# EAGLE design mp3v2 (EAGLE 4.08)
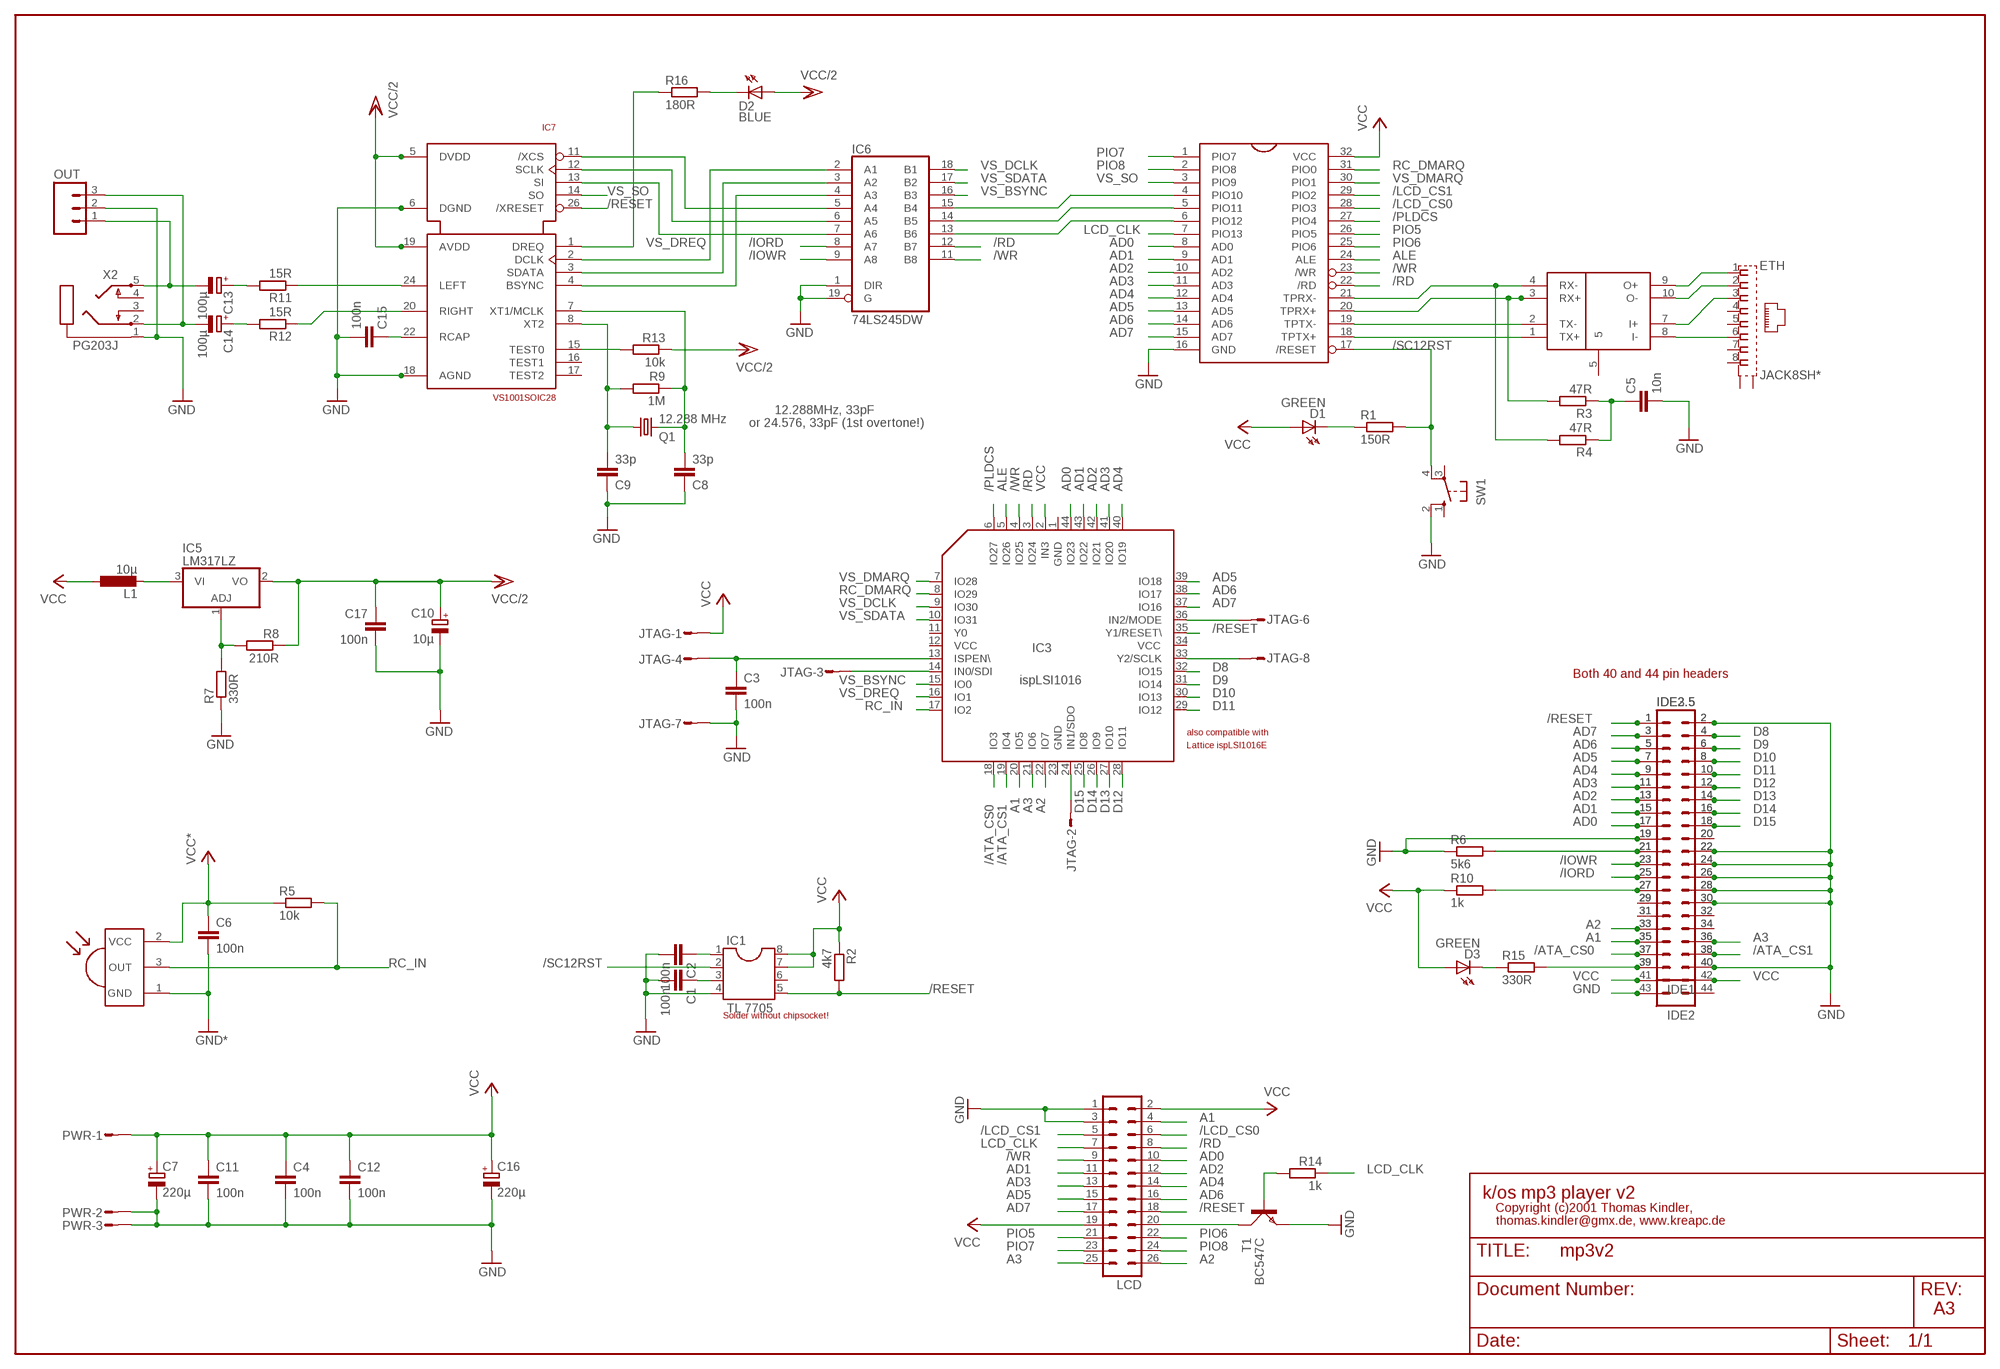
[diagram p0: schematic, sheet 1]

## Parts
C1  100n  C-EU025-024X044  [C025-024X044]
C2  100n  C-EU025-024X044  [C025-024X044]
C3  100n  C-EU025-024X044  [C025-024X044]
C4  100n  C-EU025-024X044  [C025-024X044]
C5  10n  C-EU025-024X044  [C025-024X044]
C6  100n  C-EU025-024X044  [C025-024X044]
C7  220µ  CPOL-EUE3.5-8  [E3,5-8]
C8  33p  C-EU025-024X044  [C025-024X044]
C9  33p  C-EU025-024X044  [C025-024X044]
C10  10µ  CPOL-EUE2.5-5  [E2,5-5]
C11  100n  C-EU025-024X044  [C025-024X044]
C12  100n  C-EU025-024X044  [C025-024X044]
C13  100µ  CPOL-EUE2.5-6  [E2,5-6]
C14  100µ  CPOL-EUE2.5-6  [E2,5-6]
C15  100n  C-EU025-024X044  [C025-024X044]
C16  220µ  CPOL-EUE3.5-8  [E3,5-8]
C17  100n  C-EU025-024X044  [C025-024X044]
D1  GREEN  LED3MM  [LED3MM]
D2  BLUE  LED3MM  [LED3MM]
D3  GREEN  LED3MM  [LED3MM]
ETH  JACK8SH*  [RJ45_8]
HALO  HALO  FS22-101Y4SIP10  [SIP10]
IC1  TL 7705  DIL8  [DIL08]
IC2  SC12  SC12FATDIL32  [FATDIL32]
IC3  ispLSI1016  LSI1016J  [PLCC44]
IC4  TSOP17XX*  [TSOP]
IC5  LM317LZ  [TO92@1]
IC6  74LS245DW  [SO20W]
IC7  VS1001SOIC28  [SOIC28]
IDE1  IDE3.5  ML40  [ML40]
IDE2  IDE2.5  ML44_2MM  [ML44_2MM]
JTAG  M08S  [08P]
L1  10µ  L-EU0207/12  [0207/12]
LCD  ML26  [ML26]
OUT  M03  [03P]
PWR  M03S  [03P]
Q1  12.288 MHz  HC49U-V  [HC49U-V]
R1  150R  R-EU_0207/2V  [0207/2V]
R2  4k7  R-EU_0207/2V  [0207/2V]
R3  47R  R-EU_0207/2V  [0207/2V]
R4  47R  R-EU_0207/2V  [0207/2V]
R5  10k  R-EU_0207/2V  [0207/2V]
R6  5k6  R-EU_0207/2V  [0207/2V]
R7  330R  R-EU_0207/2V  [0207/2V]
R8  210R  R-EU_0207/2V  [0207/2V]
R9  1M  R-EU_0207/2V  [0207/2V]
R10  1k  R-EU_0207/2V  [0207/2V]
R11  15R  R-EU_0207/2V  [0207/2V]
R12  15R  R-EU_0207/2V  [0207/2V]
R13  10k  R-EU_0207/2V  [0207/2V]
R14  1k  R-EU_0207/2V  [0207/2V]
R15  330R  R-EU_0207/2V  [0207/2V]
R16  180R  R-EU_0207/2V  [0207/2V]
SW1  10-XX  [B3F-10XX]
T1  BC547C  BC547  [SOT54A]
X2  PG203J  [PG203J]

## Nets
/ATA_CS0: IC3.18(IO3) IDE1.37 IDE2.37
/ATA_CS1: IC3.19(IO4) IDE1.38 IDE2.38
/IORD: IC6.8(A7) IDE1.25 IDE2.25
/IOWR: IC6.9(A8) IDE1.23 IDE2.23
/LCD_CS0: IC2.28(PIO3) LCD.6
/LCD_CS1: IC2.29(PIO2) LCD.5
/PLDCS: IC2.27(PIO4) IC3.6(IO27)
/RD: IC2.22(/RD) IC3.3(IO24) IC6.12(B7) LCD.8
/RESET: IC1.5 IC3.35(Y1/RESET\) IC7.26(/XRESET) IDE1.1 IDE2.1 LCD.18 R2.2
/SC12RST: IC1.2 IC2.17(/RESET) R1.2 SW1.4(P1)
/VS_CS: IC2.6(PIO12) IC6.13(B6)
/WR: IC2.23(/WR) IC3.4(IO25) IC6.11(B8) LCD.9
A1: IC3.20(IO5) IDE1.35 IDE2.35 LCD.4
A2: IC3.22(IO7) IDE1.33 IDE2.33 LCD.26
A3: IC3.21(IO6) IDE1.36 IDE2.36 LCD.25
AD0: IC2.8(AD0) IC3.44(IO23) IDE1.17 IDE2.17 LCD.10
AD1: IC2.9(AD1) IC3.43(IO22) IDE1.15 IDE2.15 LCD.11
AD2: IC2.10(AD2) IC3.42(IO21) IDE1.13 IDE2.13 LCD.12
AD3: IC2.11(AD3) IC3.41(IO20) IDE1.11 IDE2.11 LCD.13
AD4: IC2.12(AD4) IC3.40(IO19) IDE1.9 IDE2.9 LCD.14
AD5: IC2.13(AD5) IC3.39(IO18) IDE1.7 IDE2.7 LCD.15
AD6: IC2.14(AD6) IC3.38(IO17) IDE1.5 IDE2.5 LCD.16
AD7: IC2.15(AD7) IC3.37(IO16) IDE1.3 IDE2.3 LCD.17
ALE: IC2.24(ALE) IC3.5(IO26)
D8: IC3.32(IO15) IDE1.4 IDE2.4
D9: IC3.31(IO14) IDE1.6 IDE2.6
D10: IC3.30(IO13) IDE1.8 IDE2.8
D11: IC3.29(IO12) IDE1.10 IDE2.10
D12: IC3.28(IO11) IDE1.12 IDE2.12
D13: IC3.27(IO10) IDE1.14 IDE2.14
D14: IC3.26(IO9) IDE1.16 IDE2.16
D15: IC3.25(IO8) IDE1.18 IDE2.18
GND: C1.2 C2.2 C3.2 C4.2 C5.2 C6.2 C7.- C8.1 C9.1 C10.- C11.2 C12.2 C15.2 C16.- C17.2 IC1.4 IC2.16(GND) IC4.1(GND) IC6.1(DIR) IC6.19(G) IC7.6(DGND) IC7.10(DGND) IC7.18(AGND) IC7.21(AGND) IC7.25(AGND) IC7.27(DGND) IDE1.2 IDE1.19 IDE1.22 IDE1.24 IDE1.26 IDE1.28 IDE1.30 IDE1.40 IDE2.2 IDE2.19 IDE2.22 IDE2.24 IDE2.26 IDE2.28 IDE2.30 IDE2.40 IDE2.43 JTAG.7 LCD.1 LCD.3 OUT.2 PWR.2 PWR.3 R6.1 R7.1 SW1.2(S1) T1.E X2.1 ; supply symbol labelled GND*
LCD_CLK: IC2.7(PIO13) LCD.7 R14.1
LEFT: C13.- OUT.1 X2.5
N$1: C8.2 IC7.7(XT1/MCLK) Q1.2 R9.1
N$2: C14.+ R12.2
N$3: IDE1.39 IDE2.39 R15.2
N$4: IC6.2(A1) IC7.2(DCLK)
N$5: IC5.1(ADJ) R7.2 R8.2
N$6: HALO.4(RX-) IC2.21(TPRX-) R4.2
N$7: LCD.20 T1.C
N$8: IC7.24(LEFT) R11.1
N$9: IC7.15(TEST0) R13.2
N$10: IC6.3(A2) IC7.3(SDATA)
N$11: C15.1 IC7.22(RCAP)
N$12: C13.+ R11.2
N$13: IC7.20(RIGHT) R12.1
N$14: IC6.4(A3) IC7.4(BSYNC)
N$15: IC6.5(A4) IC7.11(/XCS)
N$16: IC6.6(A5) IC7.12(SCLK)
N$17: HALO.2(TX-) IC2.19(TPTX-)
N$18: HALO.3(RX+) IC2.20(TPRX+) R3.2
N$20: HALO.1(TX+) IC2.18(TPTX+)
N$21: ETH.1 HALO.9(O+)
N$22: ETH.2 HALO.10(O-)
N$23: ETH.3 HALO.7(I+)
N$24: ETH.6 HALO.8(I-)
N$25: C5.1 R3.1 R4.1
N$26: IC6.7(A6) IC7.13(SI)
N$27: D3.K(C) R15.1
N$28: C1.1 IC1.3
N$29: IDE1.27 IDE2.27 R10.2
N$30: C3.1 IC3.13(ISPEN\) JTAG.4
N$31: IDE1.21 IDE2.21 R6.2
N$32: C9.2 IC7.8(XT2) Q1.1 R9.2
N$33: IC3.14(IN0/SDI) JTAG.3
N$34: IC3.24(IN1/SDO) JTAG.2
N$35: IC3.36(IN2/MODE) JTAG.6
N$36: IC3.33(Y2/SCLK) JTAG.8
N$38: D2.K(C) R16.2
N$39: R14.2 T1.B
N$40: IC5.3(VI) L1.2
N$42: IDE1.29 IDE2.29
N$43: IDE1.31 IDE2.31
N$44: IDE1.20 IDE2.20
N$45: IDE1.32 IDE2.32
N$46: IDE1.34 IDE2.34
N$47: C2.1 IC1.1
N$49: D1.K(C) R1.1
PIO5: IC2.26(PIO5) LCD.21
PIO6: IC2.25(PIO6) LCD.22
PIO7: IC2.1(PIO7) LCD.23
PIO8: IC2.2(PIO8) LCD.24
RC_DMARQ: IC2.31(PIO0) IC3.8(IO29)
RC_IN: IC3.17(IO2) IC4.3(OUT) R5.2
RIGHT: C14.- OUT.3 X2.2
VCC: C4.1 C6.1 C7.+ C11.1 C12.1 C16.+ D1.A D3.A IC1.7 IC1.8 IC2.32(VCC) IC3.2(IN3) IC4.2(VCC) IDE2.41 IDE2.42 JTAG.1 L1.1 LCD.2 LCD.19 PWR.1 R2.1 R5.1 R10.1 ; supply symbol labelled VCC*
VCC/2: C10.+ C17.1 D2.A IC5.2(VO) IC7.5(DVDD) IC7.9(DVDD) IC7.19(AVDD) IC7.23(AVDD) IC7.28(DVDD) R8.1 R13.1
VS_BSYNC: IC3.15(IO0) IC6.16(B3)
VS_DCLK: IC3.9(IO30) IC6.18(B1)
VS_DMARQ: IC2.30(PIO1) IC3.7(IO28)
VS_DREQ: IC3.16(IO1) IC7.1(DREQ) R16.1
VS_SCLK: IC2.5(PIO11) IC6.14(B5)
VS_SDATA: IC3.10(IO31) IC6.17(B2)
VS_SI: IC2.4(PIO10) IC6.15(B4)
VS_SO: IC2.3(PIO9) IC7.14(SO)
Unconnected: ETH.4 ETH.5 ETH.7 ETH.8 ETH.SH1(S1) ETH.SH2(S2) HALO.5 IC1.6 IC3.11(Y0) IC7.16(TEST1) IC7.17(TEST2) IDE2.44 JTAG.5 SW1.1(S) SW1.3(P) X2.3 X2.4

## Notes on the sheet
- 12.288MHz, 33pF
- or 24.576, 33pF (1st overtone!)
- Both 40 and 44 pin headers
- also compatible with
- Lattice ispLSI1016E
- Solder without chipsocket!
- k/os mp3 player v2
- Copyright (c)2001 Thomas Kindler,
- thomas.kindler@gmx.de, www.kreapc.de
- A3

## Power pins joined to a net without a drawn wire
GND: IC3.1(GND) IC3.23(GND) IC6.10(GND)
VCC: IC3.12(VCC) IC3.34(VCC) IC6.20(VCC)

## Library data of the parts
C1-C6 C8 C9 C11 C12 C15 C17 = rcl:C-EU: CAPACITOR, European symbol
C7 C10 C13 C14 C16 = rcl:CPOL-EU: POLARIZED CAPACITOR, European symbol
D1-D3 = led:LED3MM: LED
ETH = RJ45:JACK8SH
HALO = beck:FS22-101Y4
IC1 = dil:DIL8: SOCKET DIL8
IC2 = beck:SC12
IC3 = lattice:LSI1016J: LATTICE PROGRAMMABLE DEVICE
IC4 = vishay:TSOP17XX
IC5 = linear:*317LZ: Positive VOLTAGE REGULATOR
IC6 = 74xx-eu:74*245: Octal BUS TRANSCEIVER, 3-state
IC7 = vlsi:VS1001
IDE1 = con-ml:ML40: HARTING
IDE2 = IDE44:ML44_2MM
JTAG = con-amp-quick:M08S: AMP QUICK CONNECTOR
L1 = rcl:L-EU: INDUCTOR, European symbol
LCD = con-ml:ML26: HARTING
OUT = con-amp-quick:M03: AMP QUICK CONNECTOR
PWR = con-amp-quick:M03S: AMP QUICK CONNECTOR
Q1 = crystal:HC49U-V: CRYSTAL
R1-R16 = rcl:R-EU_: RESISTOR, European symbol
SW1 = switch-omron:10-XX: OMRON SWITCH
T1 = transistor-small-signal:BC547: NPN TRANSISTOR
X2 = con-hirschmann:PG203J: MIC/HEADPHONE JACK KS-S stereo microphone/headphone jack PG203JN (Schukat)

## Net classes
0 default: width 0.254 mm
1 power: width 0.61 mm

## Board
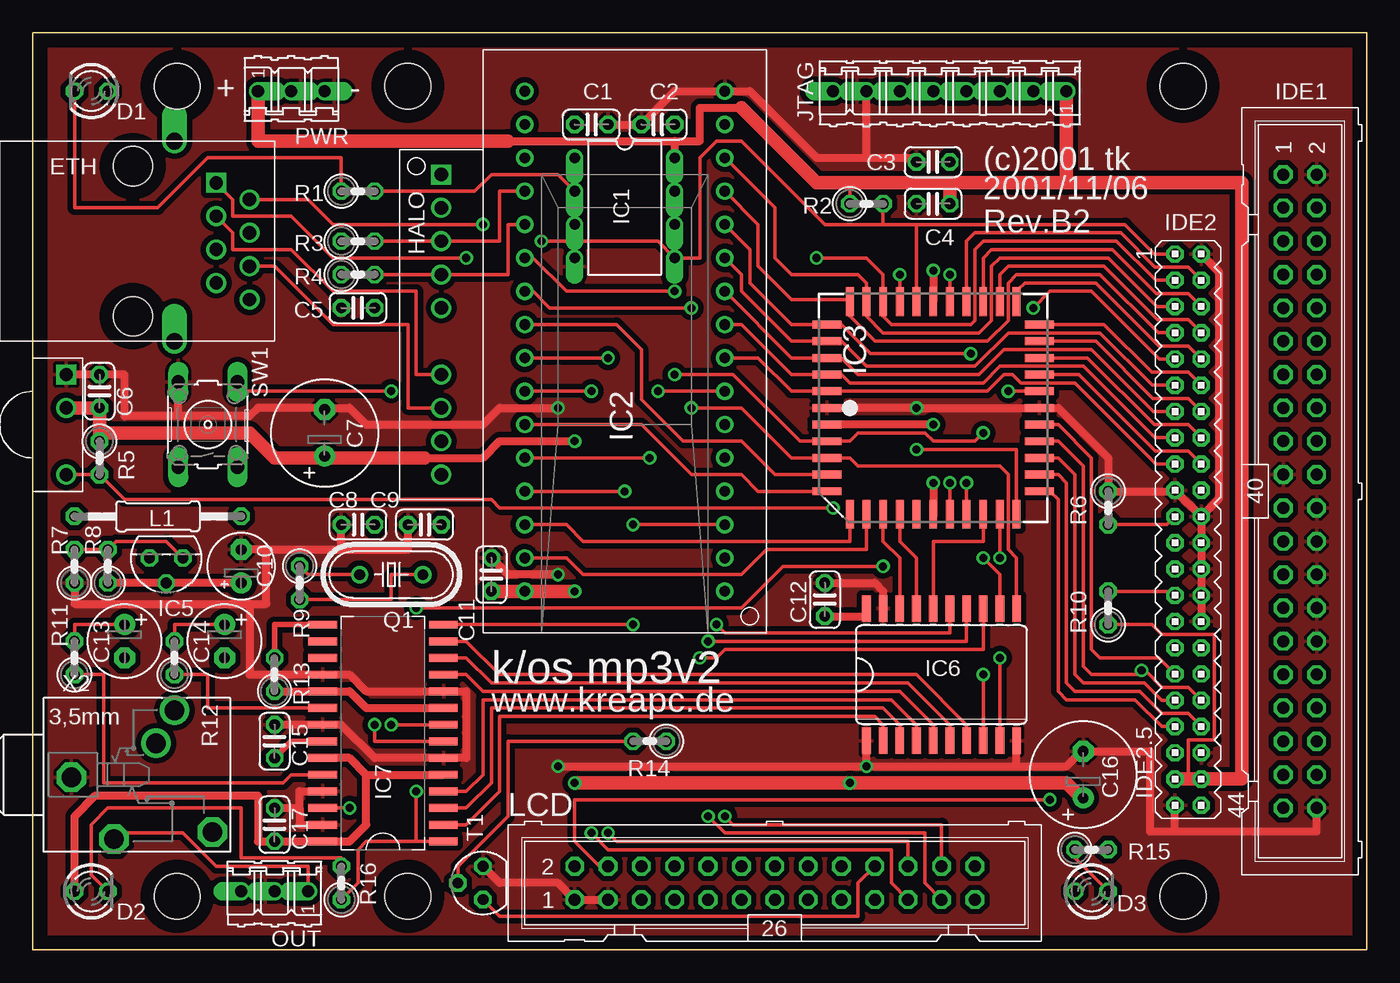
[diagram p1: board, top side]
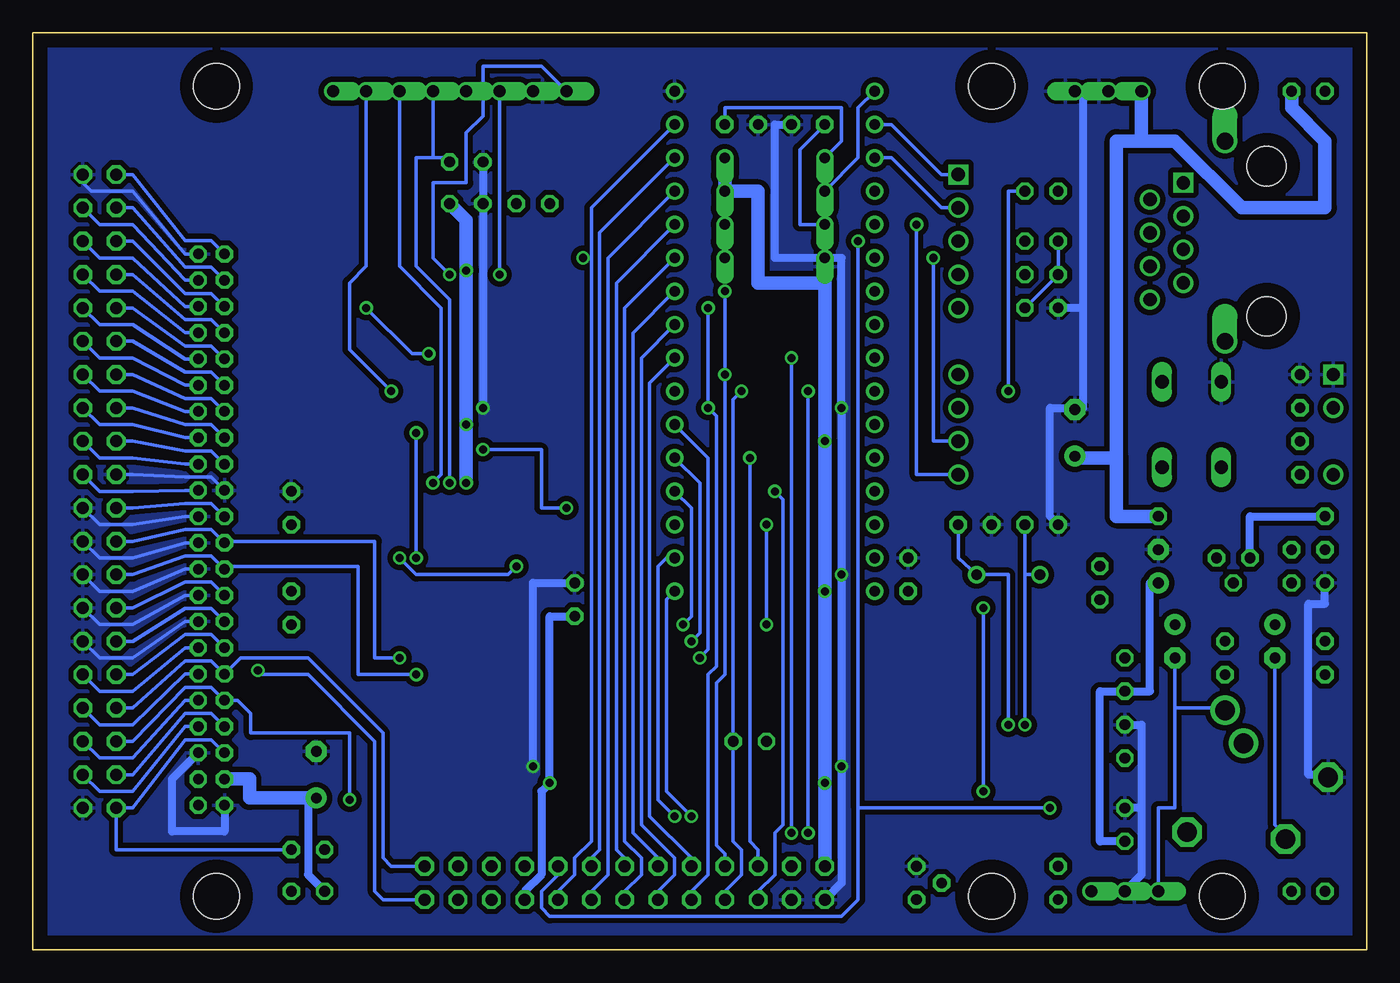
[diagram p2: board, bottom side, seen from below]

Size 101.6 x 69.85 mm. Coordinates in mm from the lower left corner, seen from the top.
Outline: 0,0 0,69.85 101.6,69.85 101.6,0 0,0
Copper layers used: Top, Bottom
Holes 3.5 mm at 87.6,4.06 11,4.06 28.57,4.06 87.6,65.79 11,65.79 28.57,65.79

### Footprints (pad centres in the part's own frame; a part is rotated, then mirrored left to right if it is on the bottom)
C025-024X044 = drill 0.813 octagon: 1 -1.27,0; 2 1.27,0
E3,5-8 = drill 0.813 pad 1.6 round: + -1.778,0 | drill 0.813 pad 1.6 octagon: - 1.778,0
E2,5-5 = drill 0.813 pad 1.6 round: + -1.27,0 | drill 0.813 pad 1.6 octagon: - 1.27,0
E2,5-6 = drill 0.813 pad 1.6 round: + -1.27,0 | drill 0.813 pad 1.6 octagon: - 1.27,0
LED3MM = drill 0.813 octagon: A -1.27,0; K 1.27,0
RJ45_8 = drill 1.016 square: 1 4.445,-6.35 | drill 1.016 round: 2 3.175,-8.89; 3 1.905,-6.35; 4 0.635,-8.89; 5 -0.635,-6.35; 6 -1.905,-8.89; 7 -3.175,-6.35; 8 -4.445,-8.89 | drill 1.27 offset: SH1 -7.62,-3.175; SH2 7.62,-3.175 | hole 3: -5.715,0; 5.715,0
SIP10 = drill 1.016 square: 1 -12.7,0 | drill 1.016 round: 2 -10.16,0; 3 -7.62,0; 4 -5.08,0; 5 -2.54,0; 7 2.54,0; 8 5.08,0; 9 7.62,0; 10 10.16,0
DIL08 = drill 0.813 offset: 1 -3.81,-3.81; 2 -1.27,-3.81; 3 1.27,-3.81; 4 3.81,-3.81; 5 3.81,3.81; 6 1.27,3.81; 7 -1.27,3.81; 8 -3.81,3.81
FATDIL32 = drill 0.813 round: 1 -19.05,-7.62; 2 -16.51,-7.62; 3 -13.97,-7.62; 4 -11.43,-7.62; 5 -8.89,-7.62; 6 -6.35,-7.62; 7 -3.81,-7.62; 8 -1.27,-7.62; 9 1.27,-7.62; 10 3.81,-7.62; 11 6.35,-7.62; 12 8.89,-7.62; 13 11.43,-7.62; 14 13.97,-7.62; 15 16.51,-7.62; 16 19.05,-7.62; 17 19.05,7.62; 18 16.51,7.62; 19 13.97,7.62; 20 11.43,7.62; 21 8.89,7.62; 22 6.35,7.62; 23 3.81,7.62; 24 1.27,7.62; 25 -1.27,7.62; 26 -3.81,7.62; 27 -6.35,7.62; 28 -8.89,7.62; 29 -11.43,7.62; 30 -13.97,7.62; 31 -16.51,7.62; 32 -19.05,7.62
PLCC44 = smd 0.6 x 2.2: 1 0,8.1; 2 -1.27,8.1; 3 -2.54,8.1; 4 -3.81,8.1; 5 -5.08,8.1; 6 -6.35,8.1; 18 -6.35,-8.1; 19 -5.08,-8.1; 20 -3.81,-8.1; 21 -2.54,-8.1; 22 -1.27,-8.1; 23 0,-8.1; 24 1.27,-8.1; 25 2.54,-8.1; 26 3.81,-8.1; 27 5.08,-8.1; 28 6.35,-8.1; 40 6.35,8.1; 41 5.08,8.1; 42 3.81,8.1; 43 2.54,8.1; 44 1.27,8.1 | smd 2.2 x 0.6: 7 -8.1,6.35; 8 -8.1,5.08; 9 -8.1,3.81; 10 -8.1,2.54; 11 -8.1,1.27; 12 -8.1,0; 13 -8.1,-1.27; 14 -8.1,-2.54; 15 -8.1,-3.81; 16 -8.1,-5.08; 17 -8.1,-6.35; 29 8.1,-6.35; 30 8.1,-5.08; 31 8.1,-3.81; 32 8.1,-2.54; 33 8.1,-1.27; 34 8.1,0; 35 8.1,1.27; 36 8.1,2.54; 37 8.1,3.81; 38 8.1,5.08; 39 8.1,6.35
TSOP = drill 1.016 square: 1 -3.81,1.27 | drill 1.016 round: 2 -1.27,1.27; 3 3.81,1.27
TO92 = drill 0.813 octagon: 1 -1.27,0; 2 0,1.905; 3 1.27,0
SO20W = smd 0.66 x 2.032: 1 -5.715,-5.029; 2 -4.445,-5.029; 3 -3.175,-5.029; 4 -1.905,-5.029; 5 -0.635,-5.029; 6 0.635,-5.029; 7 1.905,-5.029; 8 3.175,-5.029; 9 4.445,-5.029; 10 5.715,-5.029; 11 5.715,5.029; 12 4.445,5.029; 13 3.175,5.029; 14 1.905,5.029; 15 0.635,5.029; 16 -0.635,5.029; 17 -1.905,5.029; 18 -3.175,5.029; 19 -4.445,5.029; 20 -5.715,5.029
SOIC28 = smd 0.6 x 2.2: 1 -8.255,-4.6; 2 -6.985,-4.6; 3 -5.715,-4.6; 4 -4.445,-4.6; 5 -3.175,-4.6; 6 -1.905,-4.6; 7 -0.635,-4.6; 8 0.635,-4.6; 9 1.905,-4.6; 10 3.175,-4.6; 11 4.445,-4.6; 12 5.715,-4.6; 13 6.985,-4.6; 14 8.255,-4.6; 15 8.255,4.6; 16 6.985,4.6; 17 5.715,4.6; 18 4.445,4.6; 19 3.175,4.6; 20 1.905,4.6; 21 0.635,4.6; 22 -0.635,4.6; 23 -1.905,4.6; 24 -3.175,4.6; 25 -4.445,4.6; 26 -5.715,4.6; 27 -6.985,4.6; 28 -8.255,4.6
ML40 = drill 0.914 octagon: 1 -24.13,-1.27; 2 -24.13,1.27; 3 -21.59,-1.27; 4 -21.59,1.27; 5 -19.05,-1.27; 6 -19.05,1.27; 7 -16.51,-1.27; 8 -16.51,1.27; 9 -13.97,-1.27; 10 -13.97,1.27; 11 -11.43,-1.27; 12 -11.43,1.27; 13 -8.89,-1.27; 14 -8.89,1.27; 15 -6.35,-1.27; 16 -6.35,1.27; 17 -3.81,-1.27; 18 -3.81,1.27; 19 -1.27,-1.27; 20 -1.27,1.27; 21 1.27,-1.27; 22 1.27,1.27; 23 3.81,-1.27; 24 3.81,1.27; 25 6.35,-1.27; 26 6.35,1.27; 27 8.89,-1.27; 28 8.89,1.27; 29 11.43,-1.27; 30 11.43,1.27; 31 13.97,-1.27; 32 13.97,1.27; 33 16.51,-1.27; 34 16.51,1.27; 35 19.05,-1.27; 36 19.05,1.27; 37 21.59,-1.27; 38 21.59,1.27; 39 24.13,-1.27; 40 24.13,1.27
ML44_2MM = drill 0.8 octagon: 1 -21,-1; 2 -21,1; 3 -19,-1; 4 -19,1; 5 -17,-1; 6 -17,1; 7 -15,-1; 8 -15,1; 9 -13,-1; 10 -13,1; 11 -11,-1; 12 -11,1; 13 -9,-1; 14 -9,1; 15 -7,-1; 16 -7,1; 17 -5,-1; 18 -5,1; 19 -3,-1; 20 -3,1; 21 -1,-1; 22 -1,1; 23 1,-1; 24 1,1; 25 3,-1; 26 3,1; 27 5,-1; 28 5,1; 29 7,-1; 30 7,1; 31 9,-1; 32 9,1; 33 11,-1; 34 11,1; 35 13,-1; 36 13,1; 37 15,-1; 38 15,1; 39 17,-1; 40 17,1; 41 19,-1; 42 19,1; 43 21,-1; 44 21,1
08P = drill 0.914 offset: 1 -8.89,0; 2 -6.35,0; 3 -3.81,0; 4 -1.27,0; 5 1.27,0; 6 3.81,0; 7 6.35,0; 8 8.89,0
0207/12 = drill 0.813 octagon: 1 -6.35,0; 2 6.35,0
ML26 = drill 0.914 octagon: 1 -15.24,-1.27; 2 -15.24,1.27; 3 -12.7,-1.27; 4 -12.7,1.27; 5 -10.16,-1.27; 6 -10.16,1.27; 7 -7.62,-1.27; 8 -7.62,1.27; 9 -5.08,-1.27; 10 -5.08,1.27; 11 -2.54,-1.27; 12 -2.54,1.27; 13 0,-1.27; 14 0,1.27; 15 2.54,-1.27; 16 2.54,1.27; 17 5.08,-1.27; 18 5.08,1.27; 19 7.62,-1.27; 20 7.62,1.27; 21 10.16,-1.27; 22 10.16,1.27; 23 12.7,-1.27; 24 12.7,1.27; 25 15.24,-1.27; 26 15.24,1.27
03P = drill 0.914 offset: 1 -2.54,0; 2 0,0; 3 2.54,0
HC49U-V = drill 0.813 round: 1 -2.413,0; 2 2.413,0
0207/2V = drill 0.813 octagon: 1 -1.27,0; 2 1.27,0
B3F-10XX = drill 1.016 long: 1 -3.251,2.261; 2 3.251,2.261; 3 -3.251,-2.261; 4 3.251,-2.261
SOT54A = drill 0.813 octagon: B 0,1.905; C -1.27,0; E 1.27,0
PG203J = drill 1.499 octagon: 1 -5.004,-0.203; 4 5.74,-4.369; 5 -1.753,-4.902 | drill 1.499 round: 2 2.845,4.902; 3 1.448,2.388

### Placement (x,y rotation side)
C1  42.55,62.87 0 top
C2  47.62,62.87 180 top
C3  68.58,60.01 180 top
C4  68.58,56.83 180 top
C5  24.77,48.9 180 top
C6  5.08,42.55 90 top
C7  22.23,39.37 90 top
C8  24.77,32.38 0 top
C9  29.84,32.38 0 top
C10  15.88,29.21 90 top
C11  34.92,28.57 90 top
C12  60.33,26.67 90 top
C13  6.99,23.5 270 top
C14  14.61,23.5 270 top
C15  18.41,15.88 90 top
C16  80.01,13.34 90 top
C17  18.41,9.53 90 top
D1  4.45,65.41 180 top
D2  4.45,4.45 0 top
D3  80.64,4.45 0 top
ETH  7.62,53.98 90 top
HALO  31.11,46.35 270 top
IC1  45.09,56.52 270 top
IC2  45.09,46.35 90 top
IC3  68.58,41.27 90 top
IC4  1.27,40.01 270 top
IC5  LM317LZ  [TO92]  10.16,29.84 180 top
IC6  69.22,20.95 0 top
IC7  26.67,16.51 90 top
IDE1  96.52,34.92 270 top
IDE2  88,32 270 top
JTAG  69.85,65.41 180 top
L1  9.53,33.02 180 top
LCD  56.52,5.08 0 top
OUT  18.41,4.45 180 top
PWR  19.68,65.41 0 top
Q1  27.3,28.57 180 top
R1  24.77,57.78 0 top
R2  63.5,56.83 0 top
R3  24.77,53.98 0 top
R4  24.77,51.44 0 top
R5  5.08,37.47 270 top
R6  81.92,33.66 270 top
R7  3.17,29.21 90 top
R8  5.71,29.21 90 top
R9  20.32,27.94 270 top
R10  81.92,26.04 90 top
R11  3.17,22.23 90 top
R12  10.79,22.23 90 top
R13  18.41,20.95 90 top
R14  46.99,15.88 180 top
R15  80.64,7.62 0 top
R16  23.5,5.08 90 top
SW1  13.34,40.01 90 top
T1  34.29,5.08 90 top
X2  7.94,13.34 0 top

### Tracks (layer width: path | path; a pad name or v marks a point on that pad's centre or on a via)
/ATA_CS0
  Top 0.254: IC3.18 77.47,34.92 78.11,34.29 78.11,19.68 78.74,19.05 83.95,19.05 86,17 IDE2.37
  Bottom 0.254: IDE1.37 93.98,13.34 90,18 88,18 IDE2.37
/ATA_CS1
  Top 0.254: IC3.19 78.11,36.2 78.74,35.56 78.74,20.32 79.38,19.68 84.31,19.68 86,18 88,18 IDE2.38
  Bottom 0.254: IDE1.38 96.52,12.06 93.98,12.06 90,17 IDE2.38
/IORD  (via drill 0.61)
  Top 0.254: IC6.8 v72.39,20.95
  Bottom 0.254: IDE1.25 93.98,28.57 90,30 88,30 IDE2.25 86.79,29.21 76.83,29.21 76.83,20.95 v72.39,20.95
/IOWR  (via drill 0.61)
  Top 0.254: IC6.9 v73.66,22.23
  Bottom 0.254: IDE1.23 93.98,31.11 90,32 88,32 IDE2.23 86.89,31.11 75.56,31.11 75.56,22.23 v73.66,22.23
/LCD_CS0  (via drill 0.61)
  Top 0.254: v46.99,37.47 IC2.28
  Bottom 0.254: LCD.6 46.35,7.62 46.99,8.26 v46.99,37.47
/LCD_CS1  (via drill 0.61)
  Top 0.254: v45.09,34.92 IC2.29
  Bottom 0.254: LCD.5 46.35,4.45 45.09,5.71 45.09,8.89 44.45,9.53 44.45,34.29 v45.09,34.92
/PLDCS
  Top 0.254: IC3.6 55.24,34.92 53.98,36.2 50.16,36.2 46.35,40.01 IC2.27
/RD  (via drill 0.61)
  Top 0.254: v48.9,43.81 53.34,43.81 58.42,38.73 IC3.3 62.23,38.73 62.87,39.37 67.94,39.37 68.58,38.73 71.75,38.73 v72.39,39.37 | v48.9,50.16 40.64,50.16 38.1,52.7 IC2.22 | v72.39,29.84 73.66,28.57 IC6.12
  Bottom 0.254: v48.9,50.16 v48.9,43.81 48.9,20.95 49.53,20.32 49.53,7.94 48.9,7.3 LCD.8 | v72.39,39.37 v72.39,29.84
/RESET  (via drill 0.61)
  Top 0.254: 64.77,55.24 60.33,55.24 53.98,61.59 52.07,61.59 50.8,60.33 50.8,52.7 IC1.5 47.62,53.98 v38.73,53.98 | 64.77,55.24 67.31,55.24 | 67.31,55.24 IC3.35 | 67.31,55.24 83.19,55.24 85.43,53 IDE2.1 | IC7.26 v24.13,10.79 | 64.77,55.24 R2.2
  Bottom 0.254: IDE1.1 93.98,59.05 90,54 88,54 IDE2.1 | v24.13,10.79 38.73,10.79 | 38.73,10.79 v38.73,53.98 | LCD.18 61.59,5.71 62.87,4.45 62.87,3.17 62.23,2.54 40.01,2.54 38.73,3.81 38.73,10.79
/SC12RST  (via drill 0.61)
  Top 0.254: R1.2 33.66,57.78 34.92,59.05 40.01,59.05 IC1.2 | SW1.4 15.88,42.55 v27.3,42.55
  Bottom 0.254: IC2.17 38.73,64.14 38.73,60.33 IC1.2 | v27.3,42.55 27.3,57.78 R1.2
/VS_CS  (via drill 0.61)
  Top 0.254: IC6.13 72.39,22.86 52.7,22.86 52.07,22.23 v50.8,22.23
  Bottom 0.254: v50.8,22.23 50.16,22.86 50.16,37.47 IC2.6
/WR  (via drill 0.61)
  Top 0.254: v50.16,48.9 39.37,48.9 38.1,50.16 IC2.23 | v50.16,41.27 53.98,41.27 57.78,37.47 IC3.4 62.23,37.47 62.87,36.83 73.66,36.83 74.3,36.2 74.3,30.48 74.93,29.84 IC6.11
  Bottom 0.254: v50.16,48.9 v50.16,41.27 49.53,40.64 49.53,21.59 50.16,20.95 50.16,5.71 51.44,4.45 LCD.9
A1  (via drill 0.61)
  Top 0.254: IC3.20 78.11,37.47 79.38,36.2 79.38,20.95 80.01,20.32 84.68,20.32 86,19 IDE2.35 | v77.47,11.43 41.27,11.43 41.27,8.26 43.18,6.35 LCD.4
  Bottom 0.254: IDE1.35 93.98,15.88 90,20 88,20 IDE2.35 86,19 85,18 85,16.51 77.47,16.51 v77.47,11.43
A2
  Top 0.254: IC3.22 78.11,40.01 80.64,37.47 80.64,22.86 81.28,22.23 85.78,22.23 IDE2.33
  Bottom 0.254: IDE1.33 93.98,18.41 90,22 88,22 IDE2.33 85.78,22.23 80.64,22.23 74.93,16.51 74.93,6.99 74.3,6.35 LCD.26
A3  (via drill 0.61)
  Top 0.254: IC3.21 78.11,38.73 80.01,36.83 80.01,21.59 80.64,20.95 84.14,20.95 v84.45,21.27 84.73,21.27 86,20 88,20 IDE2.36
  Bottom 0.254: IDE1.36 96.52,14.61 93.98,14.61 90,19 IDE2.36 | LCD.25 74.93,3.81 75.56,4.45 75.56,15.88 80.64,20.95 84.14,20.95 v84.45,21.27
AD0
  Top 0.254: IC2.8 55.24,45.09 57.78,42.55 IC3.44 72.71,42.55 73.98,43.81 74.61,43.81 75.25,43.18 79.38,43.18 85.56,37 IDE2.17
  Bottom 0.254: IC2.8 54.61,43.18 54.61,10.16 51.44,6.99 LCD.10 | IDE1.17 93.98,38.73 90,38 88,38 IDE2.17
AD1
  Top 0.254: IC2.9 53.98,47.62 57.78,43.81 IC3.43 61.59,43.81 62.23,43.18 72.39,43.18 73.66,44.45 80.01,44.45 85.46,39 IDE2.15
  Bottom 0.254: IC2.9 55.24,45.09 55.24,9.53 52.7,6.99 52.7,5.71 53.98,4.45 LCD.11 | IDE1.15 93.98,41.27 90,40 88,40 IDE2.15
AD2
  Top 0.254: IC2.10 57.78,45.09 IC3.42 61.59,45.09 62.87,43.81 72.07,43.81 73.98,45.72 80.64,45.72 85.36,41 IDE2.13
  Bottom 0.254: IC2.10 55.88,46.99 55.88,8.89 53.98,6.99 LCD.12 | IDE1.13 93.98,43.81 90,42 88,42 IDE2.13
AD3
  Top 0.254: IC2.11 53.98,51.44 53.98,50.16 57.78,46.35 IC3.41 61.59,46.35 63.5,44.45 71.75,44.45 74.3,46.99 81.28,46.99 85.27,43 IDE2.11
  Bottom 0.254: IC2.11 56.52,48.9 56.52,8.26 55.24,6.99 55.24,5.71 56.52,4.45 LCD.13 | IDE1.11 93.98,46.35 90,44 88,44 IDE2.11
AD4  (via drill 0.61)
  Top 0.254: IC2.12 54.61,53.34 54.61,50.8 57.78,47.62 IC3.40 61.59,47.62 63.82,45.4 v71.44,45.4 | v76.2,48.9 77.47,50.16 80.64,50.16 85.81,45 IDE2.9
  Bottom 0.254: LCD.14 56.52,6.99 57.15,7.62 57.15,50.8 IC2.12 | IDE1.9 93.98,48.9 90,46 88,46 IDE2.9 | v76.2,48.9 72.71,45.4 v71.44,45.4
AD5
  Top 0.254: 62.23,49.53 IC3.39 | 62.23,49.53 62.23,48.26 64.14,46.35 72.71,46.35 74.3,47.94 74.3,50.8 74.93,51.44 81.28,51.44 85.72,47 IDE2.7 | 62.23,49.53 57.78,49.53 55.24,52.07 55.24,55.24 IC2.13
  Bottom 0.254: LCD.15 59.05,4.45 57.78,5.71 57.78,52.7 IC2.13 | IDE1.7 93.98,51.44 90,48 88,48 IDE2.7
AD6
  Top 0.254: IDE2.5 85.62,49 81.92,52.7 73.66,52.7 73.03,52.07 73.03,47.94 72.07,46.99 64.77,46.99 63.5,48.26 IC3.38 63.5,50.8 62.87,51.44 57.78,51.44 56.52,52.7 56.52,56.52 IC2.14
  Bottom 0.254: LCD.16 59.05,6.99 58.42,7.62 58.42,54.61 IC2.14 | IDE1.5 93.98,53.98 90,50 88,50 IDE2.5
AD7  (via drill 0.61)
  Top 0.254: v59.69,52.7 63.5,52.7 64.77,51.44 64.77,49.53 | IDE2.3 85.53,51 82.55,53.98 72.39,53.98 71.75,53.34 71.75,47.94 71.44,47.62 65.41,47.62 64.77,48.26 64.77,49.53 | 64.77,49.53 IC3.37
  Bottom 0.254: 59.05,52.7 59.05,56.52 IC2.15 | LCD.17 61.59,4.45 60.33,5.71 60.33,6.99 59.05,8.26 59.05,52.7 | 59.05,52.7 v59.69,52.7 | IDE1.3 93.98,56.52 90,52 88,52 IDE2.3
ALE
  Top 0.254: IC3.5 56.52,36.2 53.98,38.73 49.53,38.73 46.35,41.91 46.35,45.72 44.45,47.62 IC2.24
D8
  Top 0.254: IDE2.4 88,52 85.48,52 82.87,54.61 71.75,54.61 71.12,53.98 IC3.32
  Bottom 0.254: IDE1.4 96.52,55.24 93.98,55.24 90,51 IDE2.4
D9
  Top 0.254: IDE2.6 88,50 85.57,50 82.23,53.34 73.03,53.34 72.39,52.7 IC3.31
  Bottom 0.254: IDE1.6 96.52,52.7 93.98,52.7 90,49 IDE2.6
D10
  Top 0.254: IDE2.8 88,48 85.67,48 81.6,52.07 74.3,52.07 73.66,51.44 IC3.30
  Bottom 0.254: IDE1.8 96.52,50.16 93.98,50.16 90,47 IDE2.8
D11
  Top 0.254: IDE2.10 88,46 85.76,46 80.96,50.8 75.56,50.8 75.08,50.32 75.08,50.16 IC3.29
  Bottom 0.254: IDE1.10 96.52,47.62 93.98,47.62 90,45 IDE2.10
D12
  Top 0.254: IDE2.12 88,44 85.22,44 81.6,47.62 IC3.28
  Bottom 0.254: IDE1.12 96.52,45.09 93.98,45.09 90,43 IDE2.12
D13
  Top 0.254: IDE2.14 88,42 85.32,42 80.96,46.35 IC3.27
  Bottom 0.254: IDE1.14 96.52,42.55 93.98,42.55 90,41 IDE2.14
D14
  Top 0.254: IDE2.16 88,40 85.41,40 80.33,45.09 IC3.26
  Bottom 0.254: IDE1.16 96.52,40.01 93.98,40.01 90,39 IDE2.16
D15
  Top 0.254: IDE2.18 88,38 85.51,38 79.69,43.81 IC3.25
  Bottom 0.254: IDE1.18 96.52,37.47 93.98,37.47 90,37 IDE2.18
GND  (via drill 0.61)
  Top 0.61: 63.5,60.33 66.99,60.33 C3.2 | 60.33,41.27 IC3.1 v67.31,41.27 IC3.23 78.11,41.27 81.92,37.47 R6.1 87,34.92 87,34.93 IDE2.19 IDE2.22 | C15.2 IC7.21 23.5,17.14 26.04,14.61 IC7.6 33.02,14.61 33.02,19.68 IC7.10 25.4,19.68 24.13,20.95 IC7.18 16.51,20.95 16.51,26.35 | 20.32,10.79 20.32,12.06 IC7.25 | IC7.27 20.32,9.53 20.32,10.79 | C17.2 20.32,10.79 | IDE2.22 IDE2.24 IDE2.26 IDE2.28 IDE2.30 | IDE2.22 90.36,34.37 90.36,51.63 IDE2.2 | C1.2 C2.2 48.9,65.41 IC2.16 54.61,65.41 59.69,60.33 63.5,60.33 | 63.5,60.33 JTAG.7 | IC6.19 64.77,27.3 64.14,27.94 C12.2 | IC4.1 C6.2 6.99,43.81 6.99,40.64 11.07,40.64 | 74.93,13.97 IC6.10 | v63.5,13.97 IC6.1 | v63.5,13.97 74.93,13.97 | 74.93,13.97 78.74,13.97 79.88,15.11 C16.- 85.09,15.11 85.09,9 87,9 | v40.01,13.97 v63.5,13.97 | LCD.3 LCD.1 40.01,5.08 35.56,5.08 T1.E | 16.51,26.35 17.78,26.35 17.78,30.48 | 16.51,26.35 3.17,26.35 R7.1 | C9.1 28.57,30.48 23.5,30.48 | 23.5,30.48 C8.1 | 17.78,30.48 23.5,30.48 | 17.78,30.48 C10.- | C11.2 36.2,28.57 v40.01,28.57 | 11.07,40.64 SW1.2 | 11.07,40.64 16.51,40.64 17.14,41.27 22.23,41.27 24.13,41.27 25.4,40.01 34.29,40.01 35.56,41.27 v40.01,41.27 | IDE2.43 87,9 | IDE1.40 97.79,9 87,9
  Top 1.016: C7.- 22.23,41.27
  Bottom 0.254: IDE1.2 97.79,58.42 97.16,57.78 93.98,57.78 90,53 IDE2.2 | IDE1.30 96.52,22.23 93.98,22.23 90,25 IDE2.30 | IDE2.19 88,36 90,36 93.98,36.2 IDE1.19 | IDE1.22 96.52,32.38 93.98,32.38 90,33 IDE2.22 | IDE1.24 96.52,29.84 93.98,29.84 90,31 IDE2.24 | IDE1.26 96.52,27.3 93.98,27.3 90,29 IDE2.26 | IDE1.28 96.52,24.77 93.98,24.77 90,27 IDE2.28
  Bottom 0.61: C3.2 C4.2 v67.31,41.27 | 17.14,10.79 17.14,5.71 OUT.2 | 17.14,10.79 C17.2 | C15.2 17.14,17.14 17.14,10.79 | PWR.2 PWR.3 21.59,65.41 21.59,48.9 | LCD.1 40.01,5.08 v40.01,13.97 v40.01,28.57 v40.01,41.27 40.01,52.7 IC1.4 45.09,52.7 45.09,62.87 C1.2 | R7.1 3.17,26.35 4.45,26.35 4.45,13.34 3.17,13.34 2.97,13.13 X2.1 2.74,13.13 | 21.59,48.9 C5.2 | 22.23,41.27 21.59,41.27 21.59,48.9 | 22.23,41.27 C7.- | 22.23,41.27 24.13,41.27 24.13,33.02 C8.1 | v63.5,13.97 63.5,27.94 C12.2 | IDE2.40 91,13 91,9 87,9 IDE2.43
  pour Top (isolate 0.406): 0.64,69.22 100.97,69.22 100.97,0.64 0.64,0.64
  pour Bottom (isolate 0.406): 0.64,69.22 100.97,69.22 100.97,0.64 0.64,0.64
LCD_CLK  (via drill 0.61)
  Top 0.254: v47.62,42.55 IC2.7
  Bottom 0.254: LCD.7 48.9,4.45 47.62,5.71 47.62,7.62 48.26,8.26 R14.1 48.26,41.91 v47.62,42.55
LEFT
  Top 0.254: OUT.1 20.95,6.35 13.97,6.35 11.43,8.89 6.35,8.89 6.18,8.72 X2.5
  Bottom 0.254: C13.- 6.99,9.53 6.18,8.72 X2.5
N$1  (via drill 0.61)
  Top 0.254: v26.04,17.14 26.04,15.88 IC7.7 | R9.1 20.95,28.57 Q1.2
  Bottom 0.254: v26.04,17.14 26.04,28.57 | 26.04,28.57 C8.2 | 26.04,28.57 Q1.2
N$2
  Top 0.254: R12.2 10.79,24.77 C14.+
N$3
  Bottom 0.254: IDE2.39 88,16 90,16 93.98,10.79 IDE1.39 95.25,7.62 R15.2
N$4
  Top 0.254: IC7.2 33.02,9.53 35.56,12.06 35.56,17.78 64.14,17.78 64.77,17.14 IC6.2
N$5
  Top 0.254: R7.2 R8.2 6.35,31.11 10.16,31.11 IC5.1
N$6
  Top 0.254: IC2.21 36.2,55.24 36.2,51.44 31.75,51.44 HALO.4 30.48,51.44 R4.2
N$7
  Top 0.254: T1.C 35.56,2.54 62.87,2.54 62.87,5.08 LCD.20
N$8
  Top 0.254: IC7.24 19.68,13.34 19.05,12.7 5.4,12.7 5.4,20.95 R11.1
N$9
  Top 0.406: R13.2 18.41,24.77 IC7.15
N$10
  Top 0.254: IC7.3 33.02,10.79 34.92,12.7 34.92,18.41 64.77,18.41 66.04,17.14 IC6.3
N$11
  Top 0.406: IC7.22 19.68,15.88 C15.1
N$12
  Top 0.254: R11.2 3.17,24.77 C13.+
N$13
  Top 0.254: IC7.20 13.34,18.41 13.34,20.95 R12.1
N$14
  Top 0.254: IC7.4 33.02,12.06 34.29,13.34 34.29,19.05 65.41,19.05 67.31,17.14 IC6.4
N$15
  Top 0.254: IC7.11 33.02,20.95 34.29,19.68 66.04,19.68 68.58,17.14 IC6.5
N$16
  Top 0.254: IC7.12 33.02,22.23 34.92,20.32 66.67,20.32 69.85,17.14 IC6.6
N$17
  Bottom 0.254: IC2.19 36.2,60.33 32.38,56.52 HALO.2
N$18
  Top 0.254: IC2.20 35.56,57.78 35.56,53.98 31.75,53.98 HALO.3 30.48,53.98 R3.2
N$20
  Bottom 0.254: IC2.18 36.2,62.87 32.38,59.05 HALO.1
N$21  (via drill 0.61)
  Top 0.254: v33.02,52.7 22.86,52.7 19.68,55.88 15.24,55.88 15.24,57.15 ETH.1
  Bottom 0.254: v33.02,52.7 33.02,38.73 HALO.9
N$22  (via drill 0.61)
  Top 0.254: v34.29,55.24 22.86,55.24 20.95,57.15 ETH.2
  Bottom 0.254: v34.29,55.24 34.29,36.2 HALO.10
N$23
  Top 0.254: ETH.3 15.24,54.61 15.24,53.34 19.68,53.34 22.86,50.16 29.21,50.16 29.21,43.81 HALO.7
N$24
  Top 0.254: ETH.6 18.41,52.07 22.86,47.62 28.57,47.62 28.57,41.27 HALO.8
N$25
  Bottom 0.254: R3.1 R4.1 C5.1
N$26
  Top 0.254: IC7.13 33.02,23.5 35.56,20.95 67.31,20.95 71.12,17.14 IC6.7
N$27
  Top 0.254: D3.K 79.38,6.99 R15.1
N$28
  Bottom 0.254: C1.1 43.18,60.96 43.18,55.24 IC1.3
N$29
  Top 0.254: IDE2.27 86.36,27.3 R10.2
  Bottom 0.254: IDE1.27 93.98,26.04 90,28 88,28 IDE2.27
N$30  (via drill 0.61)
  Top 0.254: 69.85,33.02 IC3.13 v69.85,35.56
  Bottom 0.254: v69.85,35.56 69.85,49.53 72.39,52.07 72.39,60.33 71.12,60.33 | 71.12,60.33 JTAG.4 | 71.12,60.33 70.17,60.33 C3.1
N$31
  Top 0.254: IDE2.21 87,33.02 86.36,32.38 R6.2
  Bottom 0.254: IDE1.21 93.98,33.66 90,34 88,34 IDE2.21
N$32  (via drill 0.61)
  Top 0.254: v27.3,17.14 IC7.8 | R9.2 27.3,26.67 27.3,28.57 Q1.1
  Bottom 0.254: v27.3,17.14 27.3,28.57 Q1.1 31.11,29.84 C9.2
N$33  (via drill 0.61)
  Top 0.254: 71.12,33.02 IC3.14 v71.12,35.56
  Bottom 0.254: v71.12,35.56 70.48,36.2 70.48,48.9 73.66,52.07 JTAG.3
N$34  (via drill 0.61)
  Top 0.254: v74.3,42.55 IC3.24
  Bottom 0.254: v74.3,42.55 77.47,45.72 77.47,50.8 76.2,52.07 JTAG.2
N$35  (via drill 0.61)
  Top 0.254: 66.04,48.9 IC3.36 v66.04,51.44
  Bottom 0.254: v66.04,51.44 JTAG.6
N$36  (via drill 0.61)
  Top 0.254: 69.85,48.9 IC3.33 v69.85,51.44
  Bottom 0.254: v69.85,51.44 71.12,52.7 71.12,58.42 68.58,58.42 68.58,62.23 67.31,63.5 67.31,67.31 62.87,67.31 JTAG.8
N$38
  Top 0.254: R16.2 23.5,6.99 15.88,6.99 15.88,10.79 5.71,10.79 4.45,9.53 4.45,5.71 D2.K
N$39
  Top 0.254: T1.B 32.38,6.35 36.2,10.16 36.2,15.88 R14.2
N$40
  Bottom 0.61: IC5.3 8.89,33.02 L1.2 2.86,33.02
N$42
  Bottom 0.254: IDE1.29 93.98,23.5 90,26 88,26 IDE2.29
N$43
  Bottom 0.254: IDE1.31 93.98,20.95 90,24 88,24 IDE2.31
N$44
  Bottom 0.254: IDE1.20 96.52,34.92 93.98,34.92 90,35 IDE2.20
N$45
  Bottom 0.254: IDE1.32 96.52,19.68 93.98,19.68 90,23 IDE2.32
N$46
  Bottom 0.254: IDE1.34 96.52,17.14 93.98,17.14 90,21 IDE2.34
N$47
  Bottom 0.254: C2.1 48.9,64.14 40.01,64.14 40.01,61.59 IC1.1
N$49
  Top 0.254: R1.1 23.5,60.33 13.34,60.33 9.53,56.52 3.17,56.52 D1.K
PIO5  (via drill 0.61)
  Top 0.254: v42.55,42.55 IC2.26 | v42.55,8.89 43.81,7.62 65.41,7.62 65.41,5.08 LCD.21
  Bottom 0.254: v42.55,8.89 v42.55,42.55
PIO6  (via drill 0.61)
  Top 0.254: v43.81,45.09 IC2.25 | v43.81,8.89 44.45,8.26 66.67,8.26 LCD.22
  Bottom 0.254: v43.81,8.89 v43.81,45.09
PIO7  (via drill 0.61)
  Top 0.254: v51.44,10.16 52.7,8.89 67.94,8.89 67.94,5.08 LCD.23
  Bottom 0.254: IC2.1 53.34,26.67 53.34,12.06 v51.44,10.16
PIO8  (via drill 0.61)
  Top 0.254: v52.7,10.16 53.34,9.53 69.22,9.53 LCD.24
  Bottom 0.254: IC2.2 53.34,29.84 53.98,29.21 53.98,11.43 v52.7,10.16
RC_DMARQ
  Top 0.254: IC3.8 63.5,30.48 55.88,30.48 53.98,28.57 41.91,28.57 40.64,29.84 IC2.31
RC_IN  (via drill 0.61)
  Top 0.254: IC4.3 R5.2 6.99,34.29 34.92,34.29 35.56,33.66 v60.96,33.66 | v67.31,38.1 74.93,38.1 IC3.17 74.93,33.02
  Bottom 0.254: v60.96,33.66 62.87,33.66 62.87,38.1 v67.31,38.1
RIGHT
  Bottom 0.254: OUT.3 15.88,10.79 14.61,10.79 14.61,18.41 | 14.61,18.41 C14.- | X2.2 10.97,18.24 11.43,18.41 14.61,18.41
VCC  (via drill 0.61)
  Top 0.254: R10.1 85.23,24.77 86,24 90,24 90,16 88,16 88,13 IDE2.42 | 62.23,58.42 R2.1
  Top 0.61: 60.33,40.01 IC3.2 v68.58,40.01 | 68.58,33.02 IC3.12 v68.58,35.56 | 36.2,61.59 48.9,61.59 | 48.9,61.59 50.8,61.59 50.8,64.14 53.98,64.14 | v68.58,51.75 IC3.34 | 48.9,61.59 IC1.8 | IC6.20 63.5,25.4 C12.1 | 22.23,37.47 C7.+ | 29.84,37.47 34.29,37.47 35.56,38.73 v41.27,38.73
  Top 1.016: C11.1 IC2.32 v41.27,27.3 | 53.98,64.14 59.69,58.42 62.23,58.42 69.85,58.42 | 36.2,61.59 17.14,61.59 PWR.1 | 69.85,58.42 78.74,58.42 | 78.74,58.42 JTAG.1 | 69.85,58.42 C4.1 | v41.27,12.7 v62.23,12.7 78.74,12.7 79.88,11.56 C16.+ | IC4.2 C6.1 5.08,39.37 | 5.08,39.37 16.51,39.37 18.41,37.47 22.23,37.47 29.84,37.47 | R5.1 5.08,39.37 | 78.74,58.42 92.08,58.42 92.08,13 IDE2.42 | IDE2.42 89.08,13 | IDE2.41 IDE2.42
  Bottom 0.61: LCD.19 64.14,4.45 62.87,5.71 62.87,12.06 v62.23,12.7 62.23,25.4 C12.1 | C7.+ 22.23,37.47 | D3.A 80.64,5.71 80.64,11.56 C16.+
  Bottom 1.016: v68.58,35.56 v68.58,40.01 IC3.34 v68.58,51.75 68.58,55.56 C4.1 | L1.1 19.05,33.02 19.05,37.47 | IC1.8 IC1.7 46.35,57.78 46.35,50.8 41.27,50.8 v41.27,38.73 v41.27,27.3 v41.27,12.7 LCD.2 | 17.14,61.59 19.05,61.59 19.05,37.47 | 17.14,61.59 PWR.1 | 22.23,37.47 19.05,37.47 | D1.A 5.71,64.14 3.17,61.59 3.17,56.52 9.53,56.52 14.61,61.59 17.14,61.59 | IDE2.41 85.09,13 85.09,11.56 C16.+
VCC/2
  Top 0.61: R13.1 IC7.19 24.13,19.68 25.4,18.41 IC7.9 | 25.4,13.34 IC7.5 | R8.1 IC5.2 C10.+ | IC7.23 24.13,14.61 25.4,13.34 | 25.4,13.34 25.4,9.53 24.13,8.26 IC7.28 C17.1 17.14,8.26 17.14,11.75 4.76,11.75 3.17,10.16 D2.A
  Bottom 0.61: C10.+ 16.51,27.94 16.51,19.68 R13.1 20.32,19.68 20.32,8.26 C17.1
VS_BSYNC
  Top 0.254: IC3.15 72.39,31.11 68.58,31.11 IC6.16
VS_DCLK
  Top 0.254: IC6.18 66.04,29.84 64.77,31.11 IC3.9
VS_DMARQ
  Top 0.254: IC3.7 62.23,33.02 | IC3.7 62.23,33.66 | IC3.7 62.23,31.11 41.91,31.11 40.64,32.38 IC2.30
VS_DREQ  (via drill 0.61)
  Top 0.254: R16.1 24.77,5.08 24.77,7.62 25.4,8.26 29.21,8.26 | v29.21,26.04 53.98,26.04 57.15,29.21 v64.77,29.21 | 29.21,8.26 IC7.1 | 29.21,8.26 v29.21,12.06 | v73.66,29.84 IC3.16
  Bottom 0.254: v29.21,12.06 v29.21,26.04 | v64.77,29.21 65.41,28.57 72.39,28.57 v73.66,29.84
VS_SCLK  (via drill 0.61)
  Top 0.254: IC6.14 71.12,23.5 v51.44,23.5
  Bottom 0.254: v51.44,23.5 50.8,24.13 50.8,35.56 IC2.5
VS_SDATA
  Top 0.254: IC6.17 67.31,29.84 66.04,31.11 IC3.10
VS_SI  (via drill 0.61)
  Top 0.254: IC6.15 69.85,24.13 52.7,24.13 v52.07,24.77
  Bottom 0.254: v52.07,24.77 51.44,25.4 51.44,33.66 IC2.4
VS_SO  (via drill 0.61)
  Top 0.254: IC7.14 v45.72,24.77 | v45.72,32.38 IC2.3
  Bottom 0.254: v45.72,24.77 v45.72,32.38

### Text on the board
tPlace: + | - | 2001/11/06 | k/os mp3v2
tNames: (c)2001 tk | Rev.B2 | www.kreapc.de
